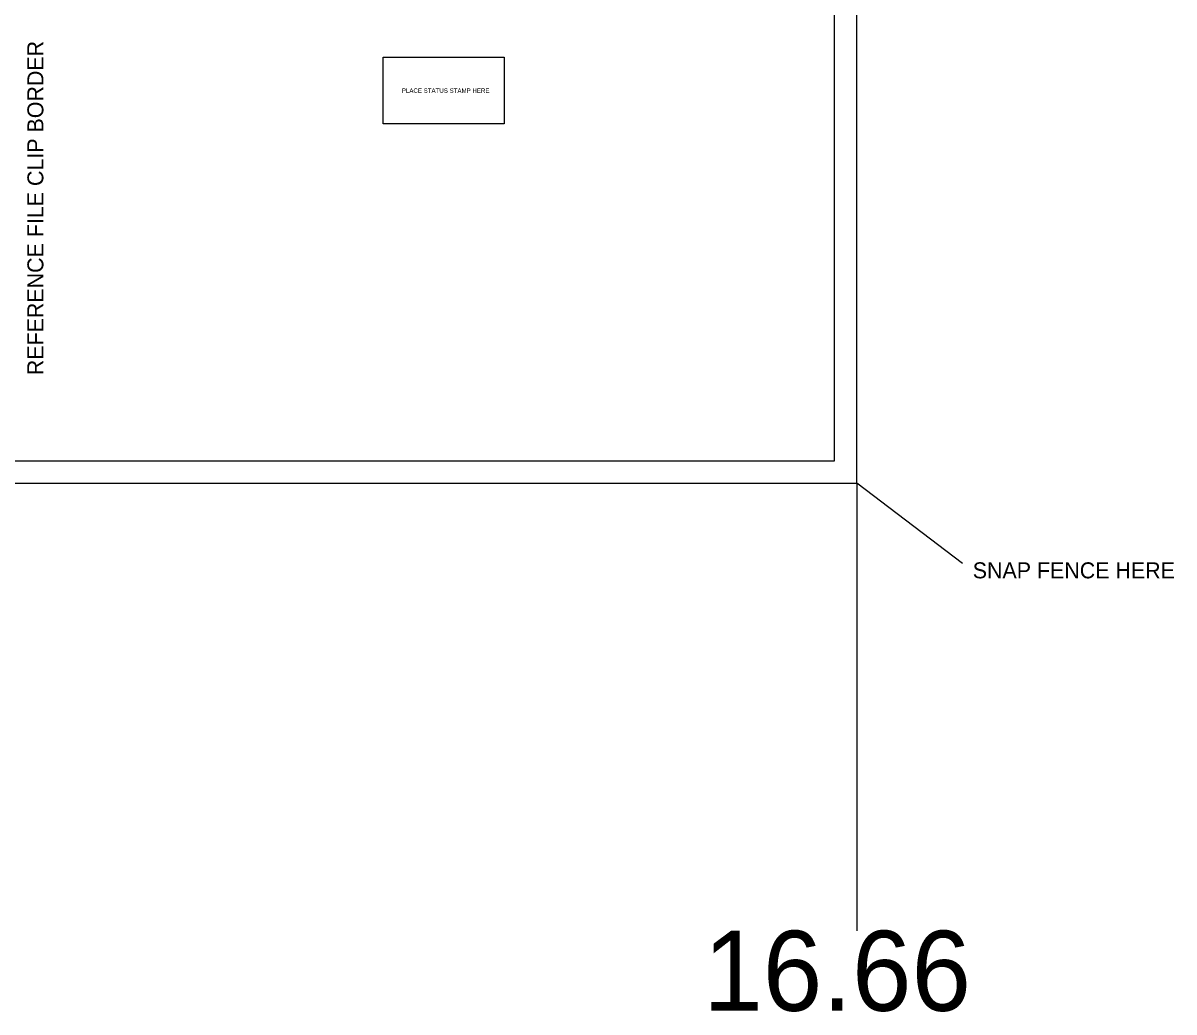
# Model space of a CAD drawing. Extents: x -1.2 to 17.3, y -1 to 2.5.
# Drawn here: x 15.103 to 17.261, y -0.991 to 0.862 of the extents above; entities that cross this region are included whole.
import ezdxf

# ---------------------------------------------------------------- set-up
doc = ezdxf.new("R2010")
doc.units = 0
for name, color, linetype in [('#plot_shape', 7, 'Continuous'), ('P_ODOT_PLAN_Border', 7, 'Continuous'), ('P_ODOT_PLAN_General', 7, 'Continuous'), ('P_RW_PLANS_DrawingTX', 7, 'Continuous')]:
    doc.layers.add(name, color=color, linetype=linetype)

msp = doc.modelspace()

# ---------------------------------------------------------------- linework, layer by layer
at = {"layer": '#plot_shape'}
msp.add_lwpolyline([(0, 0), (16.6667, 0), (16.6667, 2), (0, 2)], close=True, dxfattribs=at)
msp.add_lwpolyline([(0, 0), (16.6667, 0), (16.6667, 2), (0, 2)], close=True, dxfattribs=at)
at = {"layer": 'P_ODOT_PLAN_Border'}
for points in [[(0.0417, 0.0417), (16.625, 0.0417), (16.625, 1.9583), (0.0417, 1.9583)], [(0.0417, 0.0417), (16.625, 0.0417), (16.625, 1.9583), (0.0417, 1.9583)], [(16.0057, 0.6727), (15.7784, 0.6727), (15.7784, 0.7976), (16.0057, 0.7976)], [(16.0057, 0.6727), (15.7784, 0.6727), (15.7784, 0.7976), (16.0057, 0.7976)]]:
    msp.add_lwpolyline(points, close=True, dxfattribs=at)
at = {"layer": 'P_ODOT_PLAN_General'}
msp.add_line((16.6667, 0), (16.6667, -0.8389), dxfattribs=at)
msp.add_line((16.6667, 0), (16.6667, -0.8389), dxfattribs=at)
at = {"layer": 'P_RW_PLANS_DrawingTX'}
msp.add_line((16.8648, -0.1509), (16.6667, 0), dxfattribs=at)

# ---------------------------------------------------------------- texts
at = {"layer": 'P_ODOT_PLAN_General'}
msp.add_text('REFERENCE FILE CLIP BORDER', height=0.03, rotation=90, dxfattribs=at).set_placement((15.1416, 0.202))
msp.add_text('REFERENCE FILE CLIP BORDER', height=0.03, rotation=90, dxfattribs=at).set_placement((15.1416, 0.202))
for s, height, p in [('PLACE STATUS STAMP HERE', 0.008333, (15.8136, 0.731)), ('PLACE STATUS STAMP HERE', 0.008333, (15.8136, 0.731)), ('SNAP FENCE HERE', 0.03, (16.8839, -0.1786)), ('SNAP FENCE HERE', 0.03, (16.8839, -0.1786)), ('16.66', 0.15, (16.3787, -0.9889)), ('16.66', 0.15, (16.3787, -0.9889))]:
    msp.add_text(s, height=height, dxfattribs=at).set_placement(p)

doc.saveas('drawing.dxf')
